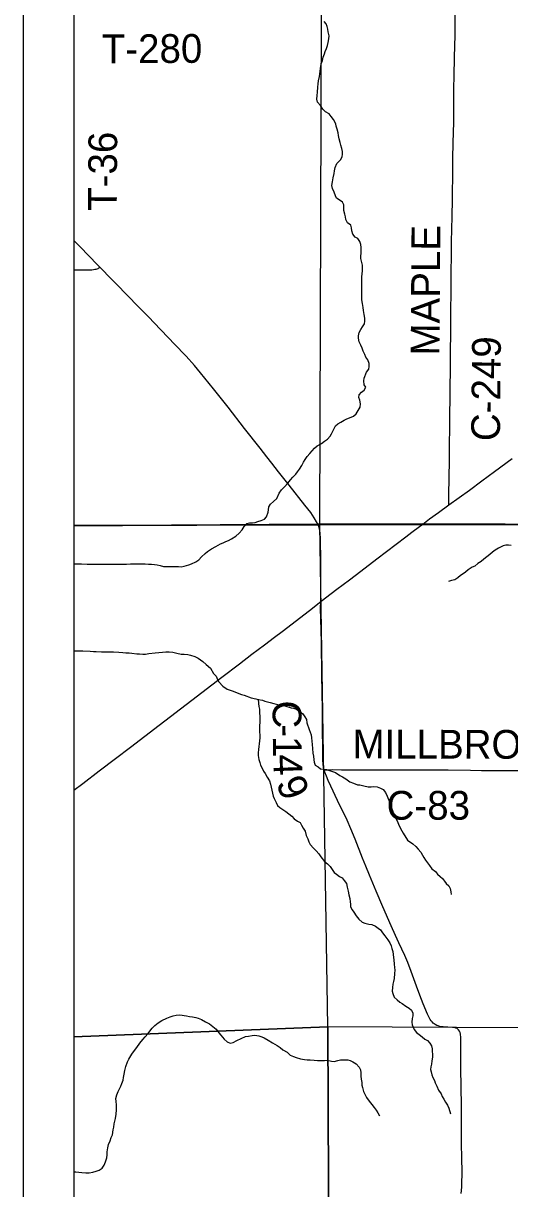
# Model space of a CAD drawing. Extents: x 0 to 34, y 0 to 22.
# Drawn here: x 2 to 2.961, y 14.561 to 16.861 of the extents above; entities that cross this region are included whole.
import ezdxf

# ---------------------------------------------------------------- set-up
doc = ezdxf.new("R2010")
doc.units = 0
for name, color, linetype in [('Default', 7, 'Continuous'), ('GM_X_County_Road', 7, 'Continuous'), ('GM_X_County_Road_Text', 7, 'Continuous'), ('GM_X_Minor_River', 7, 'Continuous'), ('GM_X_Section', 7, 'Continuous'), ('GM_X_State_Route', 7, 'Continuous'), ('GM_X_Township_Road', 7, 'Continuous'), ('GM_X_Township_Road_Text', 7, 'Continuous'), ('SH_Data', 7, 'Continuous')]:
    doc.layers.add(name, color=color, linetype=linetype)

msp = doc.modelspace()

# ---------------------------------------------------------------- linework, layer by layer
at = {"layer": 'Default'}
for points in [[(2.1, 16.8844), (2.1, 15.87), (2.5857, 15.8713), (2.5888, 16.8843)], [(2.1, 15.87), (2.1, 14.8606), (2.6012, 14.88), (2.5857, 15.8713)], [(2.1, 14.8606), (2.1, 14.1), (2.605, 14.1), (2.6012, 14.88)], [(2.605, 14.1), (3.6266, 14.1), (3.6188, 14.8751), (2.6012, 14.88)]]:
    msp.add_lwpolyline(points, close=True, dxfattribs=at)
at = {"layer": 'GM_X_County_Road'}
for points in [[(2.8407, 15.9106), (2.8407, 15.9239), (2.8408, 15.9332), (2.8411, 15.9612), (2.8419, 16.0014), (2.8419, 16.02), (2.8423, 16.0728), (2.8425, 16.0945), (2.8428, 16.1162), (2.8431, 16.1443), (2.8437, 16.1754), (2.844, 16.2002), (2.844, 16.2252), (2.8443, 16.2377), (2.8445, 16.2623), (2.8446, 16.2995), (2.8449, 16.3244), (2.8453, 16.3678), (2.8458, 16.4052), (2.8459, 16.4298), (2.8464, 16.4548), (2.8471, 16.4797), (2.8475, 16.5138), (2.8486, 16.5728), (2.8487, 16.5944), (2.8492, 16.6254), (2.8501, 16.666), (2.8501, 16.6878), (2.8503, 16.7127), (2.8505, 16.7344), (2.8507, 16.7559), (2.8515, 16.7962), (2.8521, 16.8149), (2.8528, 16.8396), (2.853, 16.8571), (2.8531, 16.8789)], [(2.1513, 16.3797), (2.1466, 16.3845), (2.112, 16.4202), (2.1, 16.4329)], [(2.5821, 15.872), (2.5794, 15.8775), (2.5746, 15.8854), (2.5676, 15.8956), (2.5562, 15.9103), (2.5253, 15.9493), (2.5043, 15.9762), (2.4908, 15.9933), (2.4813, 16.0056), (2.4678, 16.0225), (2.437, 16.0616), (2.4047, 16.1033), (2.3755, 16.1397), (2.3503, 16.1712), (2.3384, 16.1856), (2.3218, 16.204), (2.2983, 16.2288), (2.2875, 16.24), (2.2702, 16.2578), (2.2595, 16.269), (2.2464, 16.2823), (2.2333, 16.2956), (2.1992, 16.3307), (2.1902, 16.3402), (2.175, 16.3557), (2.1513, 16.3797)], [(2.5875, 15.7201), (2.588, 15.7321), (2.588, 15.7432), (2.5878, 15.7556), (2.5877, 15.7866), (2.5875, 15.8114), (2.5871, 15.8327), (2.5869, 15.8451), (2.5865, 15.8543), (2.5856, 15.8604), (2.5842, 15.8663), (2.5821, 15.872)], [(2.5943, 15.387), (2.5938, 15.3889), (2.5929, 15.3928), (2.5922, 15.3983), (2.5917, 15.4081), (2.5913, 15.4267), (2.5911, 15.4702), (2.5908, 15.5076), (2.5902, 15.5387), (2.5898, 15.5759), (2.589, 15.6381), (2.5885, 15.663), (2.5871, 15.707), (2.5875, 15.7201)], [(2.5943, 15.387), (2.6009, 15.3878), (2.61, 15.388), (2.6286, 15.3878), (2.6504, 15.3877), (2.7093, 15.3877), (2.7341, 15.3876), (2.7527, 15.3876), (2.7807, 15.3877), (2.8048, 15.3877), (2.8202, 15.3876), (2.8389, 15.3874), (2.883, 15.3868), (2.9048, 15.3864), (2.9327, 15.3862), (2.9451, 15.3863), (2.9606, 15.3862), (2.9917, 15.3861)], [(2.865, 14.5515), (2.8664, 14.5639), (2.8665, 14.5671), (2.8666, 14.595), (2.8663, 14.6199), (2.8658, 14.651), (2.8654, 14.7069), (2.8655, 14.7265), (2.865, 14.7598), (2.8645, 14.8002), (2.8644, 14.8219), (2.8642, 14.8344), (2.8642, 14.8468), (2.8641, 14.8593), (2.8636, 14.8656), (2.8629, 14.8688), (2.8616, 14.8718), (2.8596, 14.8745), (2.857, 14.8766), (2.854, 14.8779), (2.8508, 14.8787), (2.8477, 14.879), (2.8383, 14.8794), (2.829, 14.8801), (2.823, 14.881), (2.8197, 14.8821), (2.8167, 14.8831), (2.8136, 14.8847), (2.8097, 14.8876), (2.8076, 14.8898), (2.8056, 14.8921), (2.8038, 14.8945), (2.8022, 14.8971), (2.8007, 14.8997), (2.7982, 14.9053), (2.79, 14.9255), (2.7835, 14.943), (2.7769, 14.9604), (2.7664, 14.9895), (2.7595, 15.0069), (2.7534, 15.0212), (2.7417, 15.0463), (2.735, 15.0606), (2.7267, 15.0797), (2.7101, 15.1169), (2.6969, 15.148), (2.6838, 15.1796), (2.6763, 15.1977), (2.67, 15.2134), (2.6552, 15.251), (2.647, 15.2709), (2.6394, 15.2879), (2.6208, 15.3272), (2.6075, 15.3553), (2.6023, 15.3666), (2.5986, 15.3751), (2.5955, 15.3831), (2.5943, 15.387)]]:
    msp.add_lwpolyline(points, dxfattribs=at)
at = {"layer": 'GM_X_Minor_River'}
for points in [[(2.6308, 16.6031), (2.6305, 16.6081), (2.6293, 16.6145), (2.6274, 16.6206), (2.6258, 16.6263), (2.6239, 16.6335), (2.6227, 16.64), (2.622, 16.6453), (2.62, 16.6522), (2.6181, 16.6583), (2.617, 16.6632), (2.6124, 16.6716), (2.6082, 16.6773), (2.6039, 16.6826), (2.5971, 16.6864), (2.5913, 16.6921), (2.5867, 16.699), (2.5814, 16.7058), (2.5798, 16.7119), (2.5802, 16.7187), (2.5809, 16.7256), (2.5817, 16.7355), (2.5824, 16.7419), (2.5828, 16.7476), (2.5851, 16.7564), (2.5858, 16.7617), (2.5869, 16.7716), (2.5877, 16.7773), (2.5892, 16.7826), (2.5911, 16.7883), (2.5926, 16.7944), (2.5949, 16.8009), (2.5964, 16.8058), (2.5987, 16.8119), (2.6006, 16.8176), (2.6021, 16.8237), (2.6036, 16.8305), (2.6043, 16.837), (2.602, 16.8446), (2.6013, 16.8499), (2.6001, 16.8552), (2.5982, 16.8602), (2.594, 16.8651)], [(2.5567, 16.0004), (2.5609, 16.0065), (2.5658, 16.0118), (2.5704, 16.0172), (2.5754, 16.0229), (2.5807, 16.0274), (2.5887, 16.032), (2.5952, 16.0362), (2.6009, 16.0407), (2.6058, 16.046), (2.6089, 16.051), (2.6115, 16.0563), (2.6138, 16.0613), (2.6165, 16.0666), (2.6214, 16.0704), (2.6271, 16.0742), (2.634, 16.078), (2.639, 16.0806), (2.6443, 16.0822), (2.6519, 16.0856), (2.6573, 16.0905), (2.6614, 16.0973), (2.6652, 16.1038), (2.666, 16.1103), (2.6648, 16.1171), (2.6629, 16.1224), (2.6633, 16.1278), (2.6678, 16.1331), (2.6732, 16.1369), (2.6766, 16.143), (2.6735, 16.1479), (2.6724, 16.1555), (2.6735, 16.1608), (2.678, 16.1726), (2.6822, 16.1783), (2.6834, 16.1837), (2.683, 16.1897), (2.6803, 16.197), (2.6764, 16.2023), (2.6745, 16.2076), (2.6715, 16.2141), (2.6695, 16.2198), (2.6665, 16.2263), (2.6634, 16.2327), (2.6619, 16.2396), (2.6618, 16.2445), (2.6637, 16.251), (2.6668, 16.2567), (2.6698, 16.262), (2.674, 16.2681), (2.6748, 16.2734), (2.6744, 16.2795), (2.6732, 16.2867), (2.672, 16.2943), (2.6716, 16.3004), (2.6701, 16.3084), (2.6689, 16.3156), (2.6685, 16.3232), (2.6685, 16.3548), (2.6688, 16.3612), (2.6696, 16.3669), (2.6699, 16.3727), (2.6703, 16.3791), (2.6703, 16.3841), (2.6684, 16.3894), (2.6668, 16.397), (2.6668, 16.4019), (2.6672, 16.4076), (2.6672, 16.4126), (2.6672, 16.4187), (2.6664, 16.4248), (2.6648, 16.4305), (2.6606, 16.4365), (2.6557, 16.4392), (2.6507, 16.4453), (2.6488, 16.4514), (2.648, 16.4575), (2.6472, 16.4628), (2.6403, 16.4674), (2.6369, 16.4742), (2.6361, 16.4791), (2.6353, 16.4849), (2.6334, 16.4921), (2.6334, 16.4978), (2.6334, 16.5031), (2.6303, 16.5084), (2.6238, 16.513), (2.6185, 16.516), (2.6165, 16.521), (2.6138, 16.5282), (2.6104, 16.5351), (2.6092, 16.5411), (2.6104, 16.5484), (2.6123, 16.5564), (2.6138, 16.5647), (2.6149, 16.57), (2.616, 16.5769), (2.6191, 16.5849), (2.6263, 16.5921), (2.6297, 16.5978), (2.6308, 16.6031)], [(2.1, 15.7943), (2.1149, 15.7942), (2.1259, 15.7939), (2.1488, 15.7938), (2.1599, 15.7935), (2.1702, 15.7934), (2.1794, 15.7938), (2.1958, 15.7938), (2.2038, 15.7934), (2.2118, 15.7942), (2.2202, 15.7942), (2.2278, 15.7946), (2.2343, 15.7945), (2.2404, 15.7942), (2.2473, 15.7938), (2.253, 15.7934), (2.2591, 15.793), (2.2645, 15.7922), (2.2702, 15.7907), (2.2767, 15.7892), (2.2942, 15.7892), (2.3015, 15.7892), (2.3065, 15.7888), (2.3118, 15.7884), (2.3179, 15.7896), (2.3271, 15.7922), (2.3324, 15.7945), (2.3408, 15.7983), (2.3469, 15.8025), (2.3522, 15.8082), (2.3591, 15.8146), (2.364, 15.8188), (2.372, 15.8241), (2.38, 15.8287), (2.3896, 15.834), (2.3949, 15.8359), (2.3999, 15.8382), (2.4052, 15.8405), (2.4113, 15.8439), (2.4197, 15.8492), (2.4265, 15.8549), (2.4326, 15.8617), (2.4364, 15.8678), (2.4414, 15.8739), (2.4471, 15.8754), (2.4528, 15.8754), (2.4578, 15.8762), (2.4631, 15.8777), (2.4696, 15.8796), (2.4761, 15.8822), (2.4806, 15.8872), (2.4837, 15.8963), (2.484, 15.9012), (2.4848, 15.9069), (2.4882, 15.9123), (2.4943, 15.9172), (2.5008, 15.9233), (2.5053, 15.9339), (2.5099, 15.9404), (2.5156, 15.9461), (2.5225, 15.9533), (2.5278, 15.9598), (2.5327, 15.9651), (2.5381, 15.9712), (2.5419, 15.9761), (2.5457, 15.9814), (2.5503, 15.9887), (2.5537, 15.9947), (2.5567, 16.0004)], [(2.9636, 15.8306), (2.9582, 15.831), (2.9529, 15.831), (2.9475, 15.8299), (2.9384, 15.8253), (2.9319, 15.8215), (2.9266, 15.8173), (2.9212, 15.8128), (2.9155, 15.8078), (2.9098, 15.8033), (2.9041, 15.7991), (2.8976, 15.7949), (2.8919, 15.79), (2.8866, 15.7877), (2.879, 15.7827), (2.8736, 15.7778), (2.8687, 15.7744), (2.8633, 15.7713), (2.858, 15.7668), (2.8523, 15.7626), (2.8458, 15.7611), (2.8397, 15.7596)], [(2.1, 15.6222), (2.105, 15.6224), (2.1179, 15.6224), (2.1324, 15.6216), (2.1389, 15.6212), (2.1439, 15.6212), (2.1546, 15.6204), (2.1779, 15.6204), (2.1885, 15.62), (2.1969, 15.6193), (2.2027, 15.6189), (2.2088, 15.6185), (2.2141, 15.6181), (2.2241, 15.6166), (2.2298, 15.6166), (2.2359, 15.6162), (2.2412, 15.6158), (2.2481, 15.617), (2.2607, 15.6185), (2.2748, 15.62), (2.2813, 15.6204), (2.2882, 15.6204), (2.2954, 15.6196), (2.3031, 15.6181), (2.3115, 15.6162), (2.3179, 15.6158), (2.3252, 15.6154), (2.3305, 15.6142), (2.3389, 15.6116), (2.3454, 15.6082), (2.3546, 15.6017), (2.3615, 15.5956), (2.3695, 15.588), (2.3757, 15.5777), (2.381, 15.5724), (2.3833, 15.5659), (2.3864, 15.561), (2.3944, 15.553), (2.4028, 15.5469), (2.4089, 15.5446), (2.4143, 15.5431), (2.4223, 15.5393), (2.4307, 15.5366), (2.4364, 15.5351), (2.4498, 15.5298), (2.459, 15.5275), (2.4639, 15.5267), (2.4723, 15.5252), (2.4773, 15.5233), (2.4876, 15.5206), (2.4949, 15.5183), (2.4998, 15.5172), (2.5052, 15.516), (2.5102, 15.5153), (2.5166, 15.5141), (2.5289, 15.5103), (2.5338, 15.5095), (2.5396, 15.5073), (2.5461, 15.5027), (2.5518, 15.4981), (2.5564, 15.4924), (2.5591, 15.4867), (2.5602, 15.4803), (2.5648, 15.4669), (2.5668, 15.462), (2.5683, 15.4567), (2.5695, 15.451), (2.5703, 15.4377), (2.5714, 15.4297), (2.5722, 15.4205), (2.573, 15.4148), (2.5738, 15.4076), (2.5745, 15.4027), (2.5765, 15.3966), (2.5822, 15.3932), (2.5872, 15.3897), (2.5937, 15.3886)], [(2.4636, 15.5268), (2.4647, 15.5187), (2.4655, 15.5126), (2.4663, 15.5073), (2.4667, 15.5016), (2.4671, 15.4917), (2.4671, 15.4822), (2.4667, 15.4735), (2.4664, 15.4678), (2.4664, 15.4628), (2.4672, 15.456), (2.4672, 15.4506), (2.4664, 15.4446), (2.4661, 15.4392), (2.4653, 15.4339), (2.4646, 15.4278), (2.4642, 15.4214), (2.4642, 15.416), (2.4654, 15.4081), (2.4669, 15.402), (2.4688, 15.3967), (2.4715, 15.3906), (2.4746, 15.3852), (2.478, 15.3803), (2.4819, 15.3731), (2.4861, 15.3662), (2.4884, 15.359), (2.4899, 15.3533), (2.4907, 15.3476), (2.4922, 15.3415), (2.4938, 15.3358), (2.4953, 15.3309), (2.4992, 15.3229), (2.5018, 15.3172), (2.5068, 15.313), (2.5129, 15.3095), (2.5187, 15.3054), (2.5244, 15.3004), (2.5301, 15.2958), (2.5351, 15.2909), (2.5416, 15.2863), (2.5466, 15.2833), (2.5496, 15.2783), (2.5531, 15.2723), (2.5565, 15.2666), (2.5585, 15.2582), (2.5619, 15.2513), (2.5642, 15.2456), (2.5669, 15.2403), (2.5734, 15.2327), (2.5784, 15.2278), (2.5834, 15.222), (2.5876, 15.2156), (2.5952, 15.2068), (2.601, 15.2019), (2.6059, 15.1966), (2.6102, 15.1905), (2.614, 15.1851), (2.6189, 15.1817), (2.6247, 15.1771), (2.6297, 15.1745), (2.6339, 15.1688), (2.6385, 15.1634), (2.64, 15.1562), (2.6419, 15.1479), (2.6431, 15.141), (2.645, 15.1334), (2.6454, 15.1273), (2.6462, 15.1224), (2.6466, 15.1171), (2.6493, 15.1113), (2.6527, 15.1064), (2.6573, 15.0996), (2.663, 15.0927), (2.6692, 15.087), (2.6749, 15.0847), (2.6822, 15.0832), (2.6886, 15.0824), (2.6959, 15.079), (2.7009, 15.0752), (2.7058, 15.0718), (2.7093, 15.0657), (2.7139, 15.06), (2.72, 15.052), (2.7238, 15.0459), (2.7265, 15.0398), (2.7277, 15.0349), (2.7296, 15.0292), (2.7308, 15.0231), (2.7315, 15.0174), (2.7319, 15.0124), (2.7327, 15.0037), (2.7335, 14.9976), (2.7339, 14.9919), (2.7331, 14.9854), (2.7324, 14.9759), (2.7309, 14.9695), (2.7298, 14.9645), (2.729, 14.9577), (2.7286, 14.9508), (2.7302, 14.9459)], [(2.5937, 15.3886), (2.5986, 15.3882), (2.6105, 15.3844), (2.6169, 15.3825), (2.6254, 15.3764), (2.6307, 15.3737), (2.6368, 15.3696), (2.6449, 15.3638), (2.6525, 15.3612), (2.6598, 15.3577), (2.6647, 15.3577), (2.6724, 15.3558), (2.6811, 15.3543), (2.6869, 15.3543), (2.6918, 15.3547), (2.6987, 15.3543), (2.7052, 15.3516), (2.7109, 15.3486), (2.7155, 15.3429), (2.719, 15.3357), (2.7243, 15.3208), (2.727, 15.3125), (2.7293, 15.3071), (2.7313, 15.3007), (2.7336, 15.2953), (2.7378, 15.2885), (2.7431, 15.2756), (2.7477, 15.2672), (2.7504, 15.2623), (2.7589, 15.2486), (2.7696, 15.2413), (2.7753, 15.236), (2.7799, 15.2307), (2.7852, 15.225), (2.7887, 15.2193), (2.7914, 15.2143), (2.7944, 15.2094), (2.7983, 15.204), (2.8025, 15.1987), (2.8071, 15.1919), (2.8143, 15.1869), (2.8182, 15.1816), (2.8231, 15.177), (2.8281, 15.1732), (2.8319, 15.1679), (2.8354, 15.163), (2.8404, 15.1588), (2.843, 15.1531), (2.8446, 15.1466), (2.8454, 15.1417)], [(2.7302, 14.9459), (2.7325, 14.939), (2.7386, 14.9333), (2.7436, 14.9288), (2.7485, 14.9261), (2.7554, 14.9212), (2.7619, 14.917), (2.7669, 14.9128), (2.7696, 14.9075), (2.7692, 14.9021), (2.7681, 14.8968), (2.7677, 14.8896), (2.7681, 14.8839), (2.7719, 14.8751), (2.7765, 14.8691), (2.7819, 14.8649), (2.788, 14.8607), (2.793, 14.8557), (2.7983, 14.8531), (2.8029, 14.8477), (2.806, 14.8424), (2.8075, 14.8371), (2.8075, 14.8321), (2.8083, 14.8257), (2.808, 14.8204), (2.8072, 14.8128), (2.8061, 14.8067), (2.8049, 14.8013), (2.8046, 14.796), (2.8053, 14.7911), (2.8069, 14.7854), (2.8088, 14.7801), (2.8119, 14.7743), (2.8138, 14.7694), (2.8169, 14.7629), (2.8199, 14.7553), (2.8253, 14.7477), (2.8272, 14.7424), (2.8303, 14.7375), (2.8341, 14.7317), (2.8379, 14.7257), (2.8406, 14.7196), (2.8437, 14.7082)], [(2.1, 14.5938), (2.104, 14.5938), (2.1097, 14.5934), (2.1154, 14.5926), (2.1234, 14.5919), (2.1303, 14.5922), (2.1372, 14.5934), (2.1437, 14.5953), (2.1501, 14.5975), (2.1559, 14.601), (2.1597, 14.6074), (2.1623, 14.6139), (2.165, 14.6215), (2.1657, 14.6272), (2.1657, 14.6333), (2.1668, 14.6413), (2.1683, 14.6477), (2.1718, 14.6549), (2.1736, 14.6618), (2.1759, 14.6667), (2.1778, 14.6766), (2.1786, 14.6819), (2.1797, 14.6884), (2.1808, 14.6941), (2.182, 14.6994), (2.1835, 14.7078), (2.1838, 14.7162), (2.1838, 14.7261), (2.1834, 14.7325), (2.183, 14.7386), (2.1849, 14.7458), (2.1876, 14.7523), (2.1898, 14.7576), (2.1925, 14.7629), (2.1948, 14.7683), (2.1974, 14.7747), (2.1982, 14.7804), (2.1993, 14.7869), (2.2004, 14.7937), (2.2023, 14.8021), (2.2057, 14.8108), (2.2084, 14.8162), (2.2145, 14.826), (2.2179, 14.831), (2.224, 14.8393), (2.2301, 14.8481), (2.2362, 14.8549), (2.2404, 14.8602), (2.2457, 14.8667), (2.2548, 14.8774), (2.2598, 14.8827), (2.2662, 14.8884), (2.2735, 14.8929), (2.2834, 14.8971), (2.2899, 14.8998), (2.296, 14.9017), (2.3017, 14.9032), (2.3089, 14.9039), (2.3223, 14.902), (2.3284, 14.9009), (2.3341, 14.8997), (2.3406, 14.8986), (2.3456, 14.8974), (2.3517, 14.8948), (2.3601, 14.8902), (2.3681, 14.886), (2.3746, 14.8811), (2.3808, 14.8758), (2.3861, 14.8685), (2.3899, 14.8636), (2.3968, 14.856), (2.4026, 14.8506), (2.4083, 14.848), (2.4144, 14.8491), (2.4217, 14.8533), (2.43, 14.8571), (2.4392, 14.8609), (2.4449, 14.862), (2.4518, 14.8632), (2.4571, 14.8635), (2.4655, 14.8624), (2.4709, 14.8605), (2.4758, 14.8582), (2.4839, 14.8536), (2.4919, 14.8483)], [(2.4919, 14.8483), (2.5014, 14.8434), (2.5076, 14.8396), (2.5129, 14.835), (2.5209, 14.83), (2.5271, 14.8243), (2.5335, 14.8217), (2.5389, 14.8198), (2.5473, 14.8171), (2.5557, 14.8159), (2.561, 14.8152), (2.5664, 14.8152), (2.5748, 14.8144), (2.5813, 14.814), (2.5897, 14.814), (2.595, 14.8136), (2.6, 14.8144), (2.6088, 14.8125), (2.6141, 14.8121), (2.6213, 14.814), (2.6263, 14.8148), (2.6408, 14.8148), (2.6458, 14.814), (2.6507, 14.8109), (2.6572, 14.8071), (2.6634, 14.8003), (2.6657, 14.7953), (2.6664, 14.7896), (2.6668, 14.7828), (2.6676, 14.7771), (2.6684, 14.7706), (2.6688, 14.7653), (2.6699, 14.7604), (2.6719, 14.7528), (2.6745, 14.7471), (2.678, 14.7406), (2.6834, 14.7334), (2.6883, 14.7269), (2.6929, 14.7212), (2.6968, 14.7159), (2.7002, 14.7102), (2.7033, 14.7048)]]:
    msp.add_lwpolyline(points, dxfattribs=at)
at = {"layer": 'GM_X_Section'}
for points in [[(2.5888, 16.8843), (3.6155, 16.8848), (3.6011, 15.8725), (2.5857, 15.8713)], [(3.6011, 15.8725), (3.6166, 15.8725), (3.6188, 14.8751), (2.6012, 14.88), (2.5857, 15.8713)]]:
    msp.add_lwpolyline(points, close=True, dxfattribs=at)
at = {"layer": 'GM_X_State_Route'}
for points in [[(2.1, 20.9), (2.1, 15.8695), (2.5819, 15.8726), (2.7891, 15.8734), (3.6011, 15.8701), (4.6144, 15.8751)], [(2.7893, 15.8729), (2.8026, 15.8828), (2.8201, 15.8956), (2.8407, 15.9106), (2.881, 15.9399), (2.906, 15.9584), (2.931, 15.9768), (2.9657, 16.0025)], [(4.6144, 15.8751), (3.6011, 15.8701), (2.7891, 15.8734), (2.5819, 15.8726), (2.1, 15.8695), (2.1, 14.1), (5.6455, 14.1)], [(2.5907, 15.7225), (2.597, 15.7273), (2.6193, 15.7442), (2.6442, 15.7628), (2.6664, 15.7798), (2.6986, 15.8042), (2.7553, 15.8475), (2.7677, 15.8569), (2.7827, 15.8679), (2.7893, 15.8729)], [(2.1, 15.3473), (2.1179, 15.3609), (2.15, 15.3854), (2.182, 15.41), (2.2117, 15.4325), (2.2686, 15.4757), (2.3326, 15.5251), (2.3921, 15.5703), (2.427, 15.597), (2.4517, 15.6158), (2.4764, 15.6345), (2.4961, 15.6496), (2.511, 15.6609), (2.5652, 15.7024), (2.5875, 15.7201), (2.5907, 15.7225)]]:
    msp.add_lwpolyline(points, dxfattribs=at)
at = {"layer": 'GM_X_Township_Road'}
msp.add_lwpolyline([(2.1, 16.3744), (2.1138, 16.3745), (2.1292, 16.3746), (2.1354, 16.3749), (2.1387, 16.3753), (2.1414, 16.3758), (2.144, 16.3763), (2.1459, 16.3768), (2.1478, 16.3776), (2.1495, 16.3784), (2.1513, 16.3797)], dxfattribs=at)
at = {"layer": 'SH_Data'}
for p, q in [((2, 21), (2, 14)), ((2.1, 20.9), (2.1, 14.1))]:
    msp.add_line(p, q, dxfattribs=at)

# ---------------------------------------------------------------- texts
at = {"layer": 'GM_X_County_Road_Text'}
for s, height, rotation, p in [('MAPLE', 0.05682, 89.5953, (2.8219, 16.2054)), ('C-249', 0.05682, 89.4515, (2.9414, 16.0363)), ('C', 0.0568, 270.4391, (2.4923, 15.5243)), ('-', 0.0568, 270.4632, (2.4926, 15.4776)), ('MILLBROOK', 0.05682, 359.885, (2.6502, 15.4101)), ('1', 0.0568, 270.5792, (2.4928, 15.4542)), ('4', 0.0568, 272.1153, (2.4932, 15.4175)), ('9', 0.0568, 291.2073, (2.4986, 15.3624)), ('C-83', 0.05682, 0, (2.7176, 15.2891))]:
    msp.add_text(s, height=height, rotation=rotation, dxfattribs=at).set_placement(p)
at = {"layer": 'GM_X_Township_Road_Text'}
for s, rotation, p in [('T-280', 0.2811, (2.1552, 16.7825)), ('T-36', 89.6458, (2.1846, 16.491))]:
    msp.add_text(s, height=0.05682, rotation=rotation, dxfattribs=at).set_placement(p)

doc.saveas('drawing.dxf')
